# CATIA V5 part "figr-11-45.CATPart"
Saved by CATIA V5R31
Part number: Part1
Bounding box of the stored display mesh (mm): x -59 to 59, y -60 to 210, z -30 to 39.8
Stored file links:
  D:\PROJECTS\Project 2021\US EDITION\CATIA V5 6R 2021\Resources\Part Files\c11_catia_v5_6r2021_prt\figr-11-45.CATPart
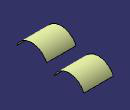
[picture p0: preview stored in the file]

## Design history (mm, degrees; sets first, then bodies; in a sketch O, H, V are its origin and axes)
AxisSystem1: origin (0, 0, 0), X (1, 0, 0), Y (0, 1, 0), Z (0, 0, 1)
AxisSystem2: origin (0, 150, -30), X (1, 0, 0), Y (0, 1, 0), Z (0, 0, 1)
Set1
  Extrude1: Element1 Sketch2, Lim1 59, Lim2 59, Direction yz-plane
  Sketch1 on yz-plane, origin (0, 0, 0), H (0, 1, 0), V (0, 0, 1)
    point P1 (150, -30)
  AxisToAxis1: ToTransfor Extrude1, AxisOrigin AxisSystem1, Axis AxisSystem2
Body1 (main body)
  Sketch2 on yz-plane, origin (0, 0, 0), H (0, 1, 0), V (0, 0, 1)
    arc A1 centre (0, -25) radius 65 from (-60, 0) to (60, 0) cw
    point P2 (-60, 0)
    point P3 (60, 0)
    coincidence: P2 H, P3 H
